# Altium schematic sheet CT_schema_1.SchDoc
size 528 x 258 mm
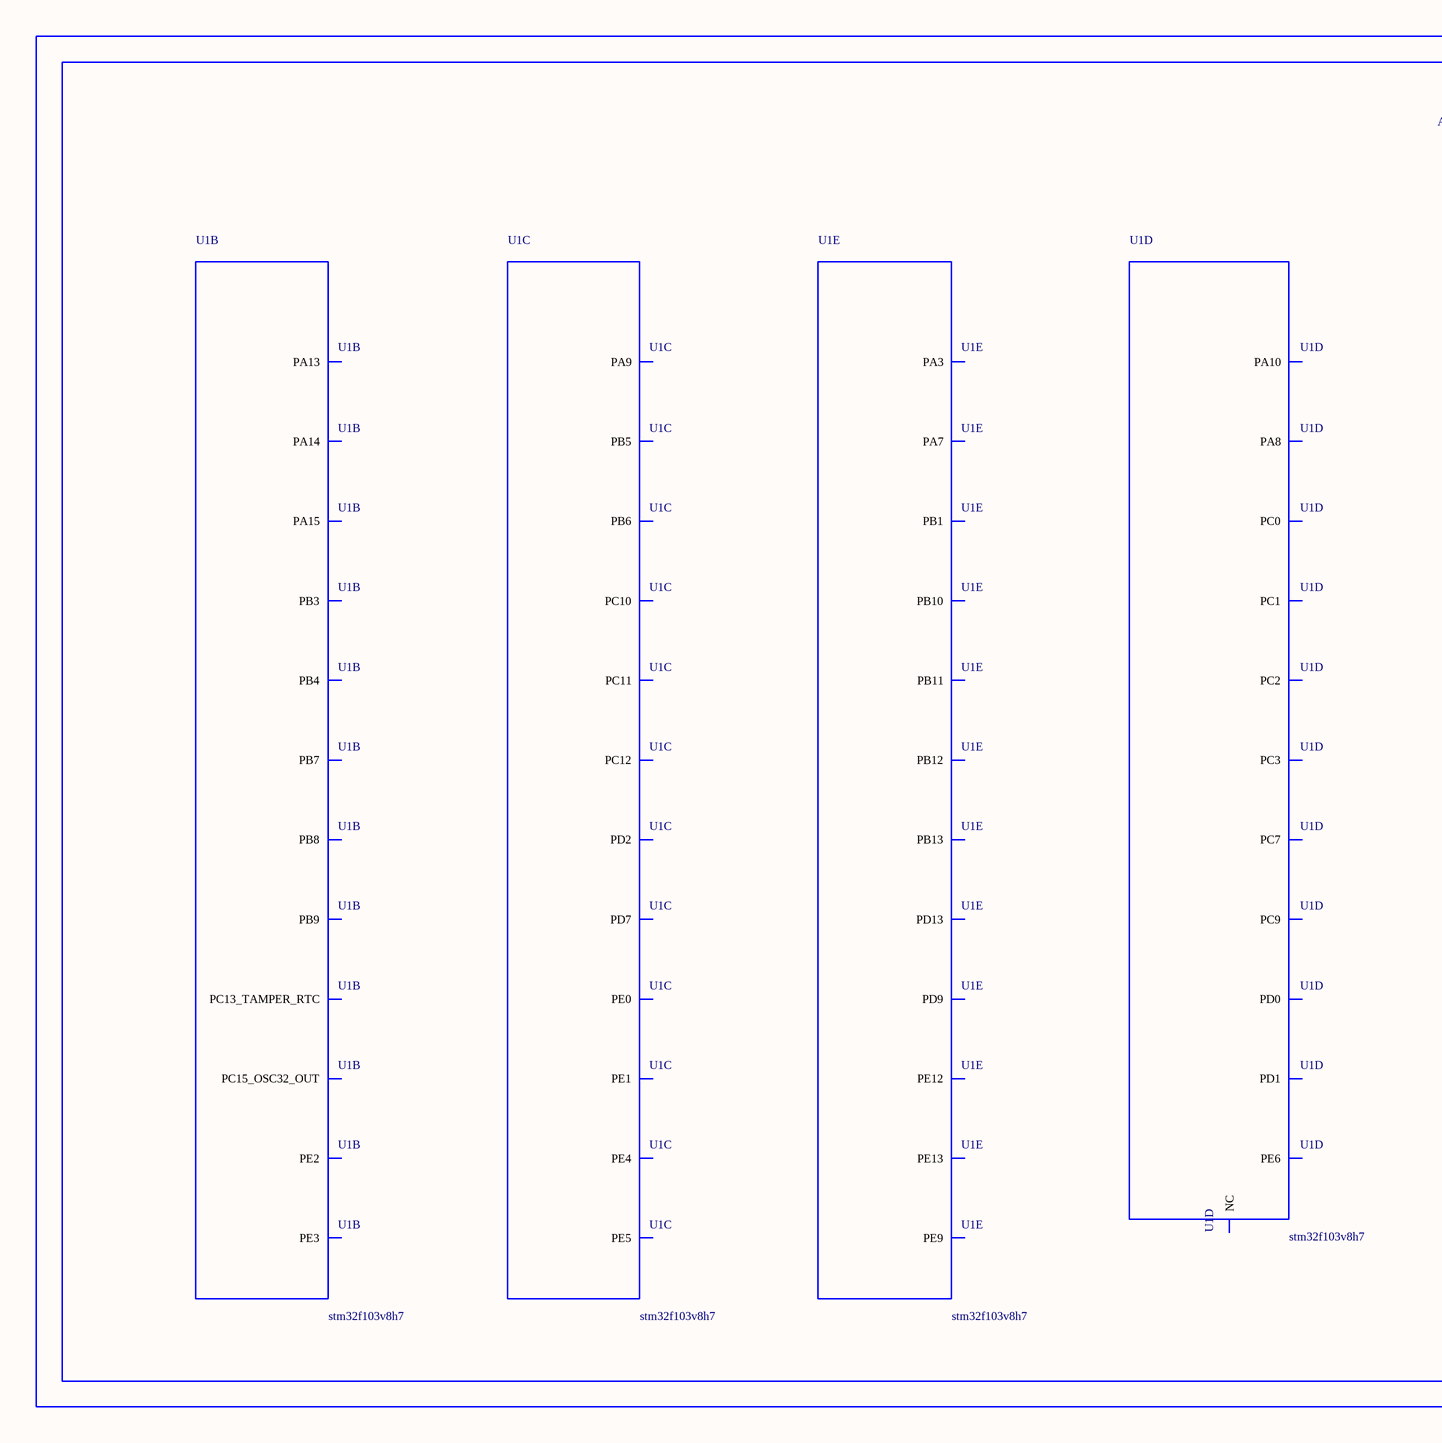
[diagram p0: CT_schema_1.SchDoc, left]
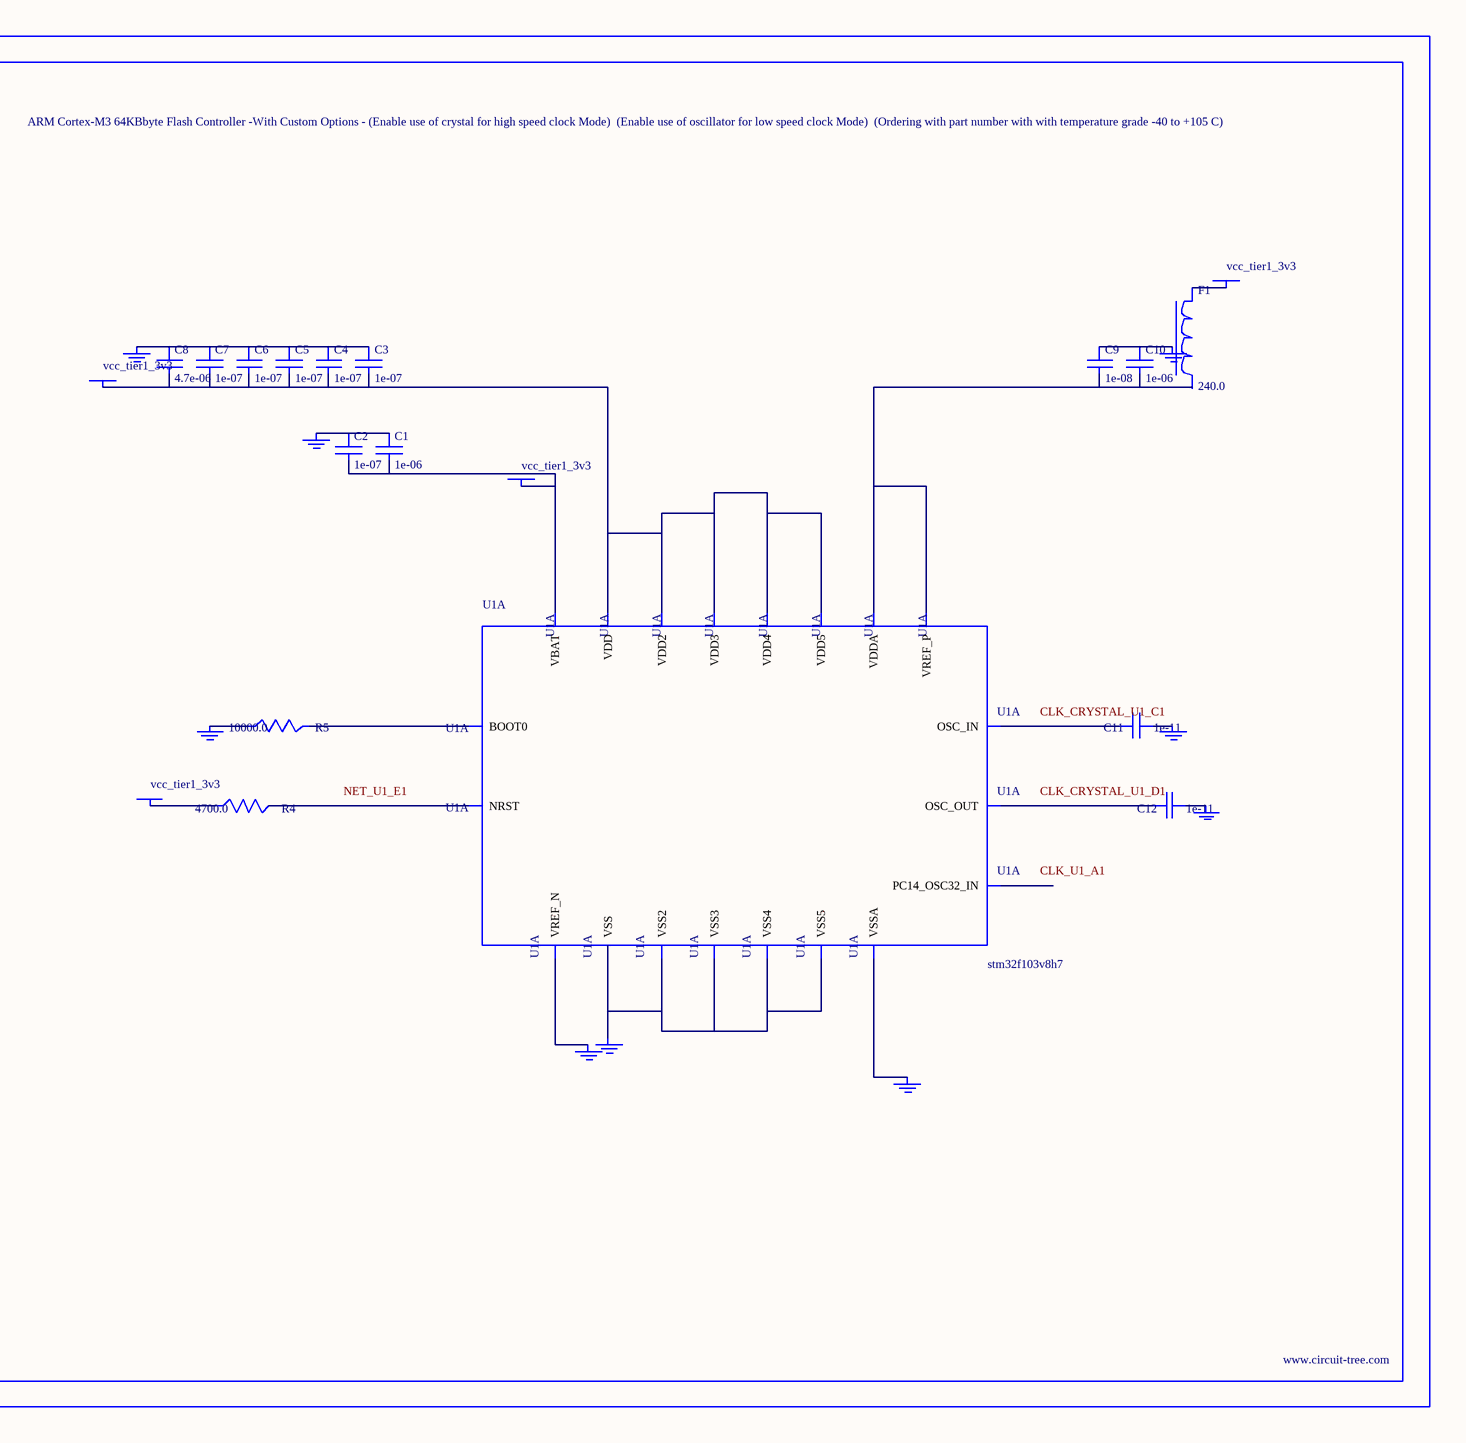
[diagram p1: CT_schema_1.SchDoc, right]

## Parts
BORDER0  (no value)
C1  1e-06  [C0603]
C2  1e-07  [C0603]
C3  1e-07  [C0603]
C4  1e-07  [C0603]
C5  1e-07  [C0603]
C6  1e-07  [C0603]
C7  1e-07  [C0603]
C8  4.7e-06  [C0603]
C9  1e-08  [C0603]
C10  1e-06  [C0603]
C11  1e-11  [C0402]
C12  1e-11  [C0402]
F1  240.0  [L0603]
GND_INSTANCE_0_0  (no value)
GND_INSTANCE_0_1  (no value)
GND_INSTANCE_0_2  (no value)
GND_INSTANCE_0_3  (no value)
GND_INSTANCE_0_4  (no value)
GND_INSTANCE_0_5  (no value)
GND_INSTANCE_0_6  (no value)
GND_INSTANCE_0_7  (no value)
GND_INSTANCE_0_8  (no value)
POWER_INSTANCE_0_0  vcc_tier1_3v3
POWER_INSTANCE_0_1  vcc_tier1_3v3
POWER_INSTANCE_0_2  vcc_tier1_3v3
POWER_INSTANCE_0_3  vcc_tier1_3v3
R4  4700.0  [R0603]
R5  10000.0  [R0603]
U1  stm32f103v8h7  [LFBGA100]  (parts A,B,C,D,E of 9)

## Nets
NetC1_1: C1.1 C2.1 GND_INSTANCE_0_0.0(GND)
NetC1_2: C1.2 C2.2 POWER_INSTANCE_0_0.0(PWR) U1.B2(VBAT)
NetC3_1: C3.1 C4.1 C5.1 C6.1 C7.1 C8.1 GND_INSTANCE_0_2.0(GND)
NetC3_2: C3.2 C4.2 C5.2 C6.2 C7.2 C8.2 POWER_INSTANCE_0_2.0(PWR) U1.D2(VDD) U1.F4(VDD2) U1.F5(VDD3) U1.F6(VDD4) U1.F7(VDD5)
NetC9_1: C9.1 C10.1 GND_INSTANCE_0_1.0(GND)
NetC9_2: C9.2 C10.2 U1.J1(VREF_P) U1.K1(VDDA)
NetC11_1: C11.1 GND_INSTANCE_0_4.0(GND)
NetC11_2: C11.2 U1.C1(OSC_IN)
NetC12_1: C12.1 GND_INSTANCE_0_5.0(GND)
NetC12_2: C12.2 U1.D1(OSC_OUT)
NetF1_1: F1.1 POWER_INSTANCE_0_1.0(PWR)
NetGND_INSTANCE_0_3_0: GND_INSTANCE_0_3.0(GND) R5.1
NetGND_INSTANCE_0_6_0: GND_INSTANCE_0_6.0(GND) U1.G1(VSSA)
NetGND_INSTANCE_0_7_0: GND_INSTANCE_0_7.0(GND) U1.H1(VREF_N)
NetGND_INSTANCE_0_8_0: GND_INSTANCE_0_8.0(GND) U1.C2(VSS) U1.E4(VSS2) U1.E5(VSS3) U1.E6(VSS4) U1.E7(VSS5)
NetPOWER_INSTANCE_0_3_0: POWER_INSTANCE_0_3.0(PWR) R4.1
NetR4_2: R4.2 U1.E1(NRST)
NetR5_2: R5.2 U1.D5(BOOT0)

Not connected (* = marked no-connect by the designer): F1 2; U1 A1(PC14_OSC32_IN) A2(PC13_TAMPER_RTC) A3(PE2) A4(PB9) A5(PB7) A6(PB4) A7(PB3) A8(PA15) A9(PA14) A10(PA13) B1(PC15_OSC32_OUT) B3(PE3) B4(PB8) B5(PB6) B7(PD2) B8(PC11) B9(PC10) C3(PE4) C4(PE1) C5(PB5) C8(PC12) C9(PA9) D3(PE5) D4(PE0) D6(PD7) D8(PD0) D9(PA8) D10(PA10) E2(PC2) E3(PE6) E8(PD1) E9(PC9) E10(PC7) F1(PC0) F2(PC1) F3(PC3) F8(NC) J6(PE12) J7(PB10) J8(PB13) J9(PD9) J10(PD13) K2(PA3) K3(PA7) K4(PB1) K5(PE9) K6(PE13) K7(PB11) K8(PB12)

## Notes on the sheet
- Labels drawn without touching a wire or pin: CLK_CRYSTAL_U1_C1, CLK_CRYSTAL_U1_D1, CLK_U1_A1, NET_U1_E1

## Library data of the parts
BORDER0 = BORDER_PAGE0
C1 C10 = C0603C105K3RACTU
C2-C7 = 06035C104K4Z2A
C8 = GRM188R6YA475KE15D
C9 = 06035C103K4Z2A
C11 C12 = C0402C100K3GACTU
F1 = Z0603C241ASMST
GND_INSTANCE_0_0-GND_INSTANCE_0_8 = GND
POWER_INSTANCE_0_0-POWER_INSTANCE_0_3 = PWR
R4 = RC0603JR-074K7L
R5 = RC0603JR-0710KL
